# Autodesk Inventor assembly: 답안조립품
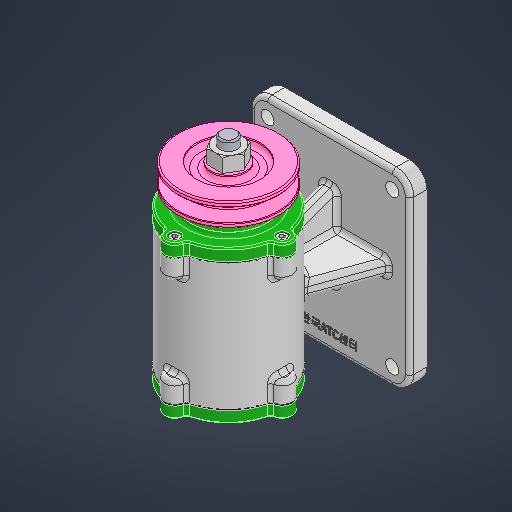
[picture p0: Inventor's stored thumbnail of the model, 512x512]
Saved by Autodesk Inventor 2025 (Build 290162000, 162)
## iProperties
Created: 2025-08
Part Number: 답안조립품
Document SubType Name: Assembly
Designer: infra14
Author: infra14
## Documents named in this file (12)
- C:\Users\infra14\Desktop\최준용\답안조립품.iam
- C:\Users\infra14\Desktop\최준용\본체.ipt
- C:\Users\infra14\Desktop\1234\공용부품_20250215_2\V-벨트풀리\V-벨트풀리.ipt
- C:\Users\infra14\Desktop\1234\공용부품_20250215_2\개스킷\개스킷.ipt
- C:\Users\infra14\Desktop\1234\공용부품_20250215_2\너트 M12 x 1.25\너트 M12 x 1.25.ipt
- C:\Users\infra14\Desktop\1234\공용부품_20250215_2\뒤커버\뒤커버.ipt
- C:\Users\infra14\Desktop\1234\공용부품_20250215_2\베어링 6204\베어링 6204.ipt
- C:\Users\infra14\Desktop\1234\공용부품_20250215_2\볼트 M4 x 12\볼트 M4 x 12.ipt
- C:\Users\infra14\Desktop\1234\공용부품_20250215_2\앞커버\앞커버.ipt
- C:\Users\infra14\Desktop\1234\공용부품_20250215_2\오일 실\오일 실.ipt
- C:\Users\infra14\Desktop\1234\공용부품_20250215_2\축\축.ipt
- C:\Users\infra14\Desktop\1234\공용부품_20250215_2\키 4 x 4\키 4 x 4.ipt
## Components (3 placed, 2 different names)
1. V-벨트풀리:1
2. 개스킷:1
3. 개스킷:2
